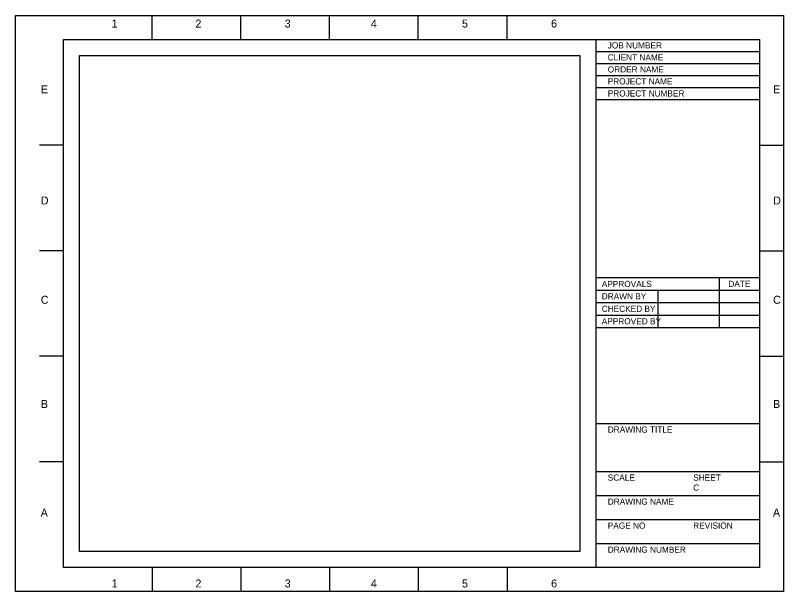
# Model space of a CAD drawing. Extents: x 0 to 2, y 0 to 1.5.
import ezdxf

# ---------------------------------------------------------------- set-up
doc = ezdxf.new("R2010")
doc.units = 0
for name, color, linetype in [('Border', 7, 'Continuous'), ('BorderPlot', 7, 'Continuous'), ('ClipShape', 7, 'Continuous'), ('TitleBlock', 7, 'Continuous'), ('TitleBlockText', 7, 'Continuous')]:
    doc.layers.add(name, color=color, linetype=linetype)

msp = doc.modelspace()

# ---------------------------------------------------------------- linework, layer by layer
at = {"layer": 'Border'}
for p, q in [((0.356, 1.4375), (0.356, 1.5)), ((0.5869, 1.4375), (0.5869, 1.5)), ((0.8179, 1.4375), (0.8179, 1.5)), ((1.0489, 1.4375), (1.0489, 1.5)), ((1.2799, 1.4375), (1.2799, 1.5)), ((1.5108, 1.4375), (1.5108, 0.0625)), ((0.125, 1.1625), (0.0625, 1.1625)), ((1.9375, 1.1625), (2, 1.1625)), ((0.125, 0.8875), (0.0625, 0.8875)), ((1.9375, 0.8875), (2, 0.8875)), ((0.125, 0.6125), (0.0625, 0.6125)), ((1.9375, 0.6125), (2, 0.6125)), ((0.125, 0.3375), (0.0625, 0.3375)), ((1.9375, 0.3375), (2, 0.3375)), ((0.356, 0.0625), (0.356, 0)), ((0.5869, 0.0625), (0.5869, 0)), ((0.8179, 0.0625), (0.8179, 0)), ((1.0489, 0.0625), (1.0489, 0)), ((1.2799, 0.0625), (1.2799, 0))]:
    msp.add_line(p, q, dxfattribs=at)
msp.add_lwpolyline([(1.9375, 0.0625), (0.125, 0.0625), (0.125, 1.4375), (1.9375, 1.4375)], close=True, dxfattribs=at)
at = {"layer": 'BorderPlot'}
msp.add_lwpolyline([(0, 1.5), (2, 1.5), (2, 0), (0, 0)], close=True, dxfattribs=at)
at = {"layer": 'ClipShape'}
for p, q in [((0.1667, 0.1042), (0.1667, 1.3958)), ((0.1667, 1.3958), (1.4692, 1.3958)), ((1.4692, 1.3958), (1.4692, 0.1042)), ((1.4692, 0.1042), (0.1667, 0.1042))]:
    msp.add_line(p, q, dxfattribs=at)
at = {"layer": 'TitleBlock'}
for p, q in [((1.5108, 1.4062), (1.9375, 1.4062)), ((1.5108, 1.375), (1.9375, 1.375)), ((1.5108, 1.375), (1.9375, 1.375)), ((1.5108, 1.3437), (1.9375, 1.3437)), ((1.5108, 1.3125), (1.9375, 1.3125)), ((1.5108, 1.3125), (1.9375, 1.3125)), ((1.5108, 1.2812), (1.9375, 1.2812)), ((1.5108, 0.8174), (1.9375, 0.8174)), ((1.8332, 0.6875), (1.8332, 0.8174)), ((1.5108, 0.7849), (1.9375, 0.7849)), ((1.5108, 0.7525), (1.9375, 0.7525)), ((1.5108, 0.72), (1.9375, 0.72)), ((1.5108, 0.6875), (1.9375, 0.6875)), ((1.5108, 0.4375), (1.9375, 0.4375)), ((1.5108, 0.3125), (1.9375, 0.3125)), ((1.5108, 0.25), (1.9375, 0.25)), ((1.5108, 0.25), (1.9375, 0.25)), ((1.5108, 0.1875), (1.9375, 0.1875)), ((1.5108, 0.1875), (1.9375, 0.1875)), ((1.5108, 0.125), (1.9375, 0.125)), ((1.9375, 0.0625), (1.9375, 0.0625))]:
    msp.add_line(p, q, dxfattribs=at)
at = {"layer": 'TitleBlockText'}
msp.add_line((1.6736, 0.6875), (1.6736, 0.7849), dxfattribs=at)

# ---------------------------------------------------------------- texts
at = {"layer": 'Border'}
for s, p in [('1', (0.2504, 1.4683)), ('2', (0.4688, 1.4683)), ('3', (0.7012, 1.4683)), ('4', (0.9255, 1.4683)), ('5', (1.1627, 1.4683)), ('6', (1.3946, 1.4683)), ('E', (0.0664, 1.297)), ('E', (1.9727, 1.297)), ('D', (0.0663, 1.0077)), ('D', (1.9726, 1.0077)), ('C', (0.0663, 0.7493)), ('C', (1.9726, 0.7493)), ('B', (0.0663, 0.478)), ('B', (1.9726, 0.478)), ('A', (0.0659, 0.1952)), ('A', (1.9722, 0.1952)), ('1', (0.2504, 0.0109)), ('2', (0.4688, 0.0109)), ('3', (0.7012, 0.0109)), ('4', (0.9255, 0.0109)), ('5', (1.1627, 0.0109)), ('6', (1.3946, 0.0109))]:
    msp.add_text(s, height=0.0208, dxfattribs=at).set_placement(p)
at = {"layer": 'TitleBlockText'}
for s, height, p in [('JOB NUMBER', 0.0161, (1.5421, 1.4138)), ('CLIENT NAME', 0.016098, (1.5421, 1.3826)), ('ORDER NAME', 0.0161, (1.5421, 1.3513)), ('PROJECT NAME', 0.016098, (1.5421, 1.3201)), ('PROJECT NUMBER', 0.016098, (1.5421, 1.2888)), ('APPROVALS', 0.0161, (1.5265, 0.7929)), ('DATE', 0.0161, (1.8561, 0.7931)), ('DRAWN BY', 0.0161, (1.5265, 0.7607)), ('CHECKED BY', 0.0161, (1.5265, 0.7282)), ('APPROVED BY', 0.016098, (1.5265, 0.6957)), ('DRAWING TITLE', 0.016098, (1.5421, 0.4138)), ('SCALE', 0.0161, (1.5421, 0.2888)), ('SHEET', 0.0161, (1.7646, 0.2888)), ('C', 0.0161, (1.7646, 0.2628)), ('DRAWING NAME', 0.016098, (1.5421, 0.2263)), ('PAGE NO', 0.0161, (1.5421, 0.1638)), ('REVISION', 0.0161, (1.7646, 0.1638)), ('DRAWING NUMBER', 0.016098, (1.5421, 0.1013))]:
    msp.add_text(s, height=height, dxfattribs=at).set_placement(p)

doc.saveas('drawing.dxf')
